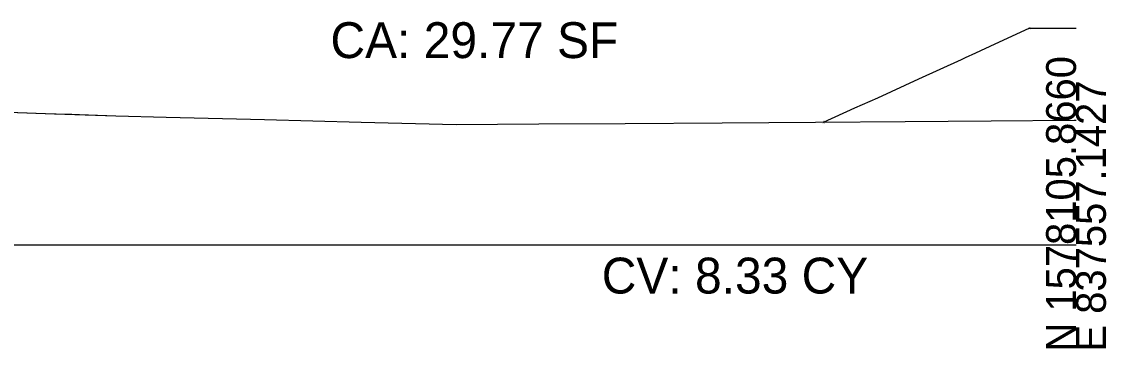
# Model space of a CAD drawing. Extents: x -26 to 303, y -16 to 6048.
# Drawn here: x 201.2 to 302.8, y 2990.3 to 3020.9 of the extents above; entities that cross this region are included whole.
import ezdxf

# ---------------------------------------------------------------- set-up
doc = ezdxf.new("R2010")
doc.units = 0
for name, color, linetype in [('DTM_P_FINISHED_GRADE', 7, 'Continuous'), ('DTM_TEMP_DROP', 7, 'Continuous'), ('DTM_X_FLOW_ARROWS', 7, 'Continuous'), ('DTM_X_GROUND', 7, 'Continuous'), ('XS_CELL', 7, 'Continuous'), ('XS_P_GROUND', 7, 'Continuous'), ('XS_SHEET_EW_TX_AREA', 7, 'Continuous'), ('XS_SHEET_EW_TX_VOLUME', 7, 'Continuous')]:
    doc.layers.add(name, color=color, linetype=linetype)

msp = doc.modelspace()

# ---------------------------------------------------------------- linework, layer by layer
at = {"layer": 'DTM_P_FINISHED_GRADE'}
msp.add_lwpolyline([(295.61, 3020.3), (300, 3020.3)], dxfattribs=at)
at = {"layer": 'DTM_X_GROUND'}
for points in [[(195.7, 3012.58), (204.28, 3012.28), (210.04, 3012.09), (214.74, 3011.98), (223.95, 3011.74), (233.01, 3011.51), (241.91, 3011.28), (249.65, 3011.35), (257.74, 3011.37), (266.85, 3011.44), (275.59, 3011.5), (283.99, 3011.57), (292.06, 3011.63), (299.83, 3011.69), (300, 3011.69)], [(199.02, 3012.46), (204.28, 3012.28), (204.44, 3012.27), (205.71, 3012.23), (205.89, 3012.23), (206.29, 3012.21), (206.62, 3012.2), (210.04, 3012.09), (214.74, 3011.98), (223.95, 3011.74), (233.01, 3011.51), (241.91, 3011.28), (249.65, 3011.35), (257.74, 3011.37), (266.85, 3011.44), (275.59, 3011.5), (283.99, 3011.57), (292.06, 3011.63), (299.83, 3011.69), (300, 3011.69)]]:
    msp.add_lwpolyline(points, dxfattribs=at)
at = {"layer": 'XS_CELL'}
msp.add_line((150, 3000), (300, 3000), dxfattribs=at)
at = {"layer": 'XS_P_GROUND'}
msp.add_lwpolyline([(276.34, 3011.51), (279.28, 3012.83), (281.42, 3013.79), (285.28, 3015.55), (289.26, 3017.37), (289.64, 3017.54), (290.6, 3017.98), (292.43, 3018.83), (295.61, 3020.3)], dxfattribs=at)

# ---------------------------------------------------------------- texts
at = {"layer": 'DTM_TEMP_DROP'}
msp.add_text('X', height=0.24, dxfattribs=at).set_placement((295.53, 3020.18))
at = {"layer": 'DTM_X_FLOW_ARROWS'}
msp.add_text('X', height=0.24, dxfattribs=at).set_placement((276.26, 3011.39))
at = {"layer": 'XS_CELL'}
for s, p in [('N 1578105.8660', (300, 2990)), ('E 837557.1427', (302.8, 2990))]:
    msp.add_text(s, height=2.8, rotation=90, dxfattribs=at).set_placement(p)
at = {"layer": 'XS_SHEET_EW_TX_AREA'}
msp.add_text('CA: 29.77 SF', height=3.36, dxfattribs=at).set_placement((230.14, 3017.5))
at = {"layer": 'XS_SHEET_EW_TX_VOLUME'}
msp.add_text('CV: 8.33 CY', height=3.36, dxfattribs=at).set_placement((255.56, 2995.44))

doc.saveas('drawing.dxf')
